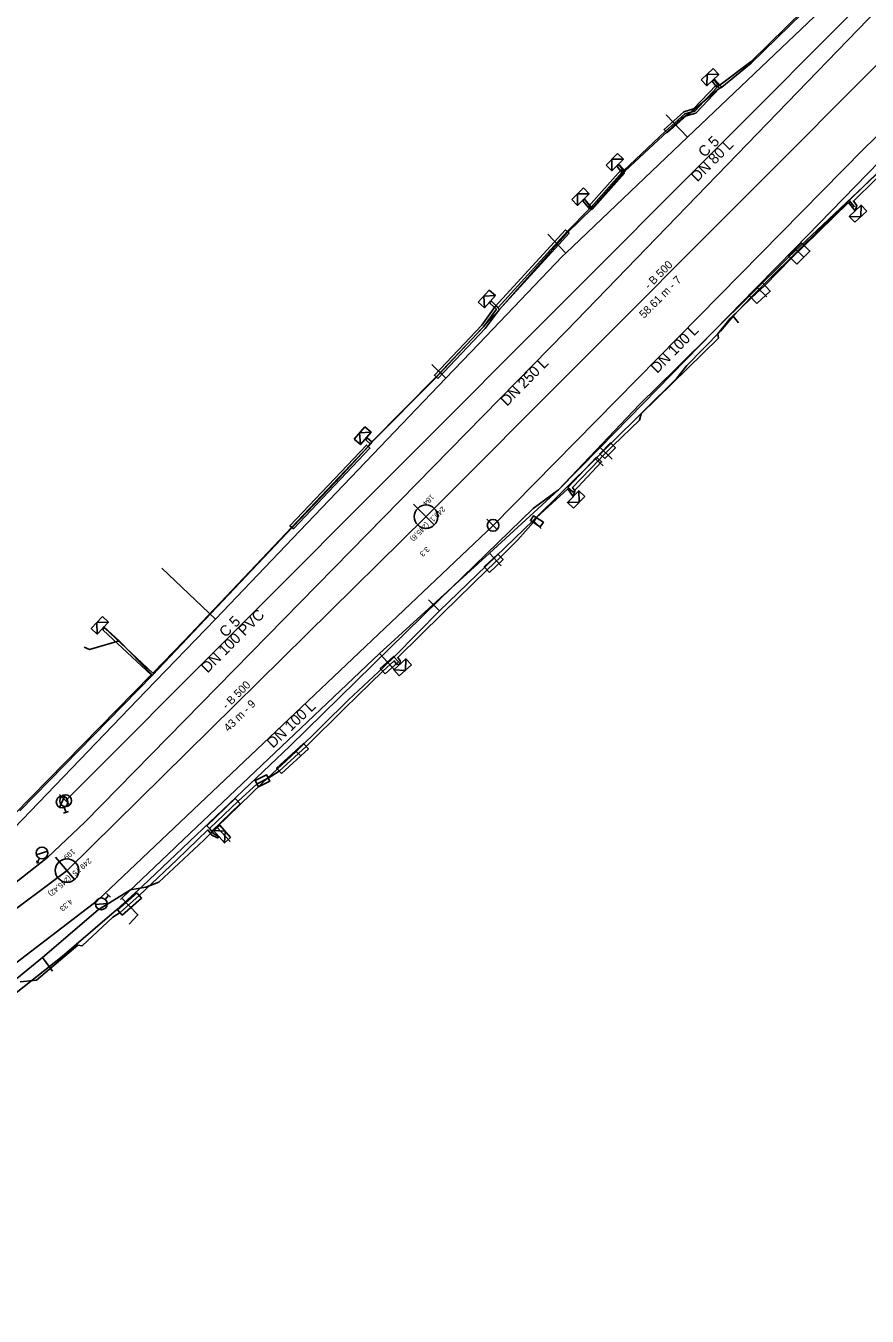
# Model space of a CAD drawing. Extents: x -600636 to -600148, y -1203980 to -1203569.
# Drawn here: x -600456.1 to -600384.3, y -1203740.1 to -1203630.1 of the extents above; entities that cross this region are included whole.
import ezdxf

# ---------------------------------------------------------------- set-up
doc = ezdxf.new("R2010")
doc.units = 0
for name, color, linetype in [('Cetin zam průběh', 7, 'Continuous'), ('EON podzemní NN', 7, 'Continuous'), ('GasNet NTL', 7, 'Continuous'), ('Implicitní', 7, 'Continuous'), ('VaK Břeclav_kanalizace', 7, 'Continuous'), ('VaK Břeclav_kanalizace_popis', 7, 'Continuous'), ('Vak Břeclav_vodovod', 7, 'Continuous'), ('Vak Břeclav_vodovod_popis', 7, 'Continuous'), ('Vrstva 9', 7, 'Continuous')]:
    doc.layers.add(name, color=color, linetype=linetype)

# ---------------------------------------------------------------- blocks, each defined once
blk = doc.blocks.new('NN630')
at = {"layer": 'Vrstva 9'}
for points in [[(0, -0.7), (-0.7, 0)], [(-0.7, -0.7), (-0.7, 0), (0.7, 0), (0.7, -0.7)], [(-0.7, -0.7), (0.7, -0.7)], [(0, -0.7), (0.7, 0)]]:
    blk.add_lwpolyline(points, dxfattribs=at)
blk = doc.blocks.new('MoSymbol 2')
at = {"layer": 'Implicitní'}
blk.add_line((0, 0.0005), (0, -0.00075), dxfattribs=at)
blk.add_circle((0, 0), 0.0005, dxfattribs=at)
blk = doc.blocks.new('MoSymbol 3')
at = {"layer": 'Implicitní'}
for p, q in [((-0.000365, -0.000365), (0.000365, 0.000365)), ((-0.000225, 0.00095), (0.000225, 0.00095)), ((0, 0.00095), (0, 0.0005))]:
    blk.add_line(p, q, dxfattribs=at)
blk.add_circle((0, 0), 0.0005, dxfattribs=at)
blk = doc.blocks.new('MoSymbol 5')
at = {"layer": 'Implicitní'}
for p, q in [((-0.000365, -0.000365), (0.000365, 0.000365)), ((0, 0.00095), (0.0001, 0.0008))]:
    blk.add_line(p, q, dxfattribs=at)
blk.add_lwpolyline([(0, 0.0005), (0, 0.00095), (-0.0001, 0.0008)], dxfattribs=at)
blk.add_circle((0, 0), 0.0005, dxfattribs=at)

msp = doc.modelspace()

# ---------------------------------------------------------------- linework, layer by layer
at = {"layer": 'Cetin zam průběh'}
for points in [[(-600403.75, -1203662.4), (-600400.59, -1203659.29), (-600391.04, -1203649.83), (-600378.25, -1203637.79), (-600376.97, -1203637.47), (-600375.66, -1203637.95), (-600375.36, -1203637.74), (-600369.01, -1203633.38), (-600361.52, -1203627.61), (-600348.82, -1203618.06), (-600335.53, -1203608.82), (-600318.11, -1203596.27), (-600313.64, -1203592.14)], [(-600396.73, -1203635.32), (-600394.24, -1203633.29), (-600389.88, -1203629.05)], [(-600385.87, -1203644.99), (-600379.24, -1203638.53), (-600378.07, -1203637.95), (-600377.04, -1203637.82), (-600374.96, -1203638.83), (-600373.66, -1203638.86), (-600369.62, -1203634.3), (-600368.09, -1203632.74)], [(-600396.73, -1203635.32), (-600397.41, -1203634.6)], [(-600404.98, -1203642.46), (-600400.14, -1203637.98), (-600399.49, -1203637.58), (-600397.06, -1203635.49), (-600396.73, -1203635.32)], [(-600399.49, -1203637.58), (-600397.06, -1203635.49)], [(-600404.98, -1203642.46), (-600405.35, -1203642.11), (-600405.51, -1203641.95)], [(-600407.82, -1203645.71), (-600404.98, -1203642.46)], [(-600407.82, -1203645.71), (-600408.44, -1203644.89)], [(-600395.78, -1203654.85), (-600394.24, -1203653.23), (-600393.19, -1203652.19), (-600392.21, -1203651.23), (-600390.95, -1203650.01), (-600389.97, -1203649.02), (-600385.87, -1203644.99)], [(-600385.87, -1203644.99), (-600385.42, -1203645.53)], [(-600415.71, -1203654.29), (-600409.87, -1203647.71), (-600407.82, -1203645.71)], [(-600421.21, -1203660.21), (-600415.71, -1203654.29), (-600409.87, -1203647.71)], [(-600390.95, -1203650.01), (-600389.97, -1203649.02)], [(-600394.24, -1203653.23), (-600393.19, -1203652.19)], [(-600426.6, -1203665.62), (-600421.21, -1203660.21), (-600415.71, -1203654.29)], [(-600415.71, -1203654.29), (-600416.41, -1203653.56)], [(-600407.51, -1203667.04), (-600407.25, -1203666.78), (-600406.25, -1203665.78), (-600400.57, -1203660.14), (-600399.71, -1203659.07), (-600396.85, -1203656.15), (-600395.78, -1203654.85)], [(-600395.78, -1203654.85), (-600395.31, -1203655.42)], [(-600412.83, -1203671.25), (-600410.66, -1203669.68), (-600403.75, -1203662.4)], [(-600426.6, -1203665.62), (-600426.99, -1203665.22)], [(-600445.32, -1203685.49), (-600433.34, -1203672.82), (-600429.69, -1203669.02), (-600426.84, -1203665.93), (-600426.6, -1203665.62)], [(-600433.34, -1203672.82), (-600429.69, -1203669.02), (-600426.84, -1203665.93)], [(-600407.25, -1203666.78), (-600406.25, -1203665.78)], [(-600412.82, -1203672.3), (-600407.51, -1203667.04)], [(-600407.51, -1203667.04), (-600406.87, -1203667.62)], [(-600433.58, -1203691.53), (-600420.86, -1203679.06), (-600412.83, -1203671.25)], [(-600420.82, -1203679.99), (-600412.82, -1203672.3)], [(-600412.82, -1203672.3), (-600412.16, -1203672.98)], [(-600421.75, -1203679.05), (-600420.82, -1203679.99)], [(-600433.06, -1203691.99), (-600428.59, -1203687.58), (-600425.61, -1203684.8), (-600424.64, -1203683.87), (-600420.82, -1203679.99)], [(-600448.15, -1203682.56), (-600449.48, -1203681.33)], [(-600448.15, -1203682.56), (-600450.67, -1203683.28), (-600451.15, -1203683.08)], [(-600445.32, -1203685.49), (-600448.15, -1203682.56)], [(-600424.64, -1203683.87), (-600425.61, -1203684.8)], [(-600456.63, -1203697.04), (-600445.32, -1203685.49)], [(-600446.15, -1203703.46), (-600433.58, -1203691.53)], [(-600439.83, -1203698.44), (-600435.92, -1203694.67), (-600433.06, -1203691.99)], [(-600433.06, -1203691.99), (-600435.92, -1203694.67)], [(-600433.06, -1203691.99), (-600432.67, -1203692.34)], [(-600454.7, -1203709.55), (-600449.93, -1203705.5), (-600447.19, -1203703.78), (-600445.87, -1203703.57), (-600444.77, -1203703.13), (-600440.93, -1203699.54), (-600439.83, -1203698.44)], [(-600440.93, -1203699.54), (-600439.83, -1203698.44)], [(-600439.83, -1203698.44), (-600438.69, -1203699.66)], [(-600453.01, -1203709.48), (-600448.37, -1203705.5), (-600446.15, -1203703.46)], [(-600447.19, -1203703.78), (-600445.87, -1203703.57)], [(-600490.14, -1203736.91), (-600480.27, -1203730.01), (-600469.5, -1203722.46), (-600453.01, -1203709.48)], [(-600465.84, -1203718.51), (-600459.73, -1203713.66), (-600454.7, -1203709.55)], [(-600454.7, -1203709.55), (-600453.84, -1203710.72)]]:
    msp.add_lwpolyline(points, dxfattribs=at)
at = {"layer": 'EON podzemní NN'}
for points in [[(-600457.12, -1203697.36), (-600445.42, -1203685.44), (-600449.51, -1203681.63), (-600449.55, -1203681.46), (-600449.38, -1203681.48), (-600445.28, -1203685.3), (-600442.61, -1203682.55), (-600433.43, -1203672.87), (-600426.9, -1203665.99), (-600426.73, -1203665.74), (-600427.09, -1203665.43), (-600427.11, -1203665.28), (-600426.96, -1203665.28), (-600426.6, -1203665.59), (-600421.1, -1203660.04), (-600417.07, -1203655.76), (-600415.96, -1203654.26), (-600416.51, -1203653.77), (-600416.52, -1203653.62), (-600416.37, -1203653.62), (-600415.83, -1203654.11), (-600409.92, -1203647.64), (-600408.02, -1203645.71), (-600408.58, -1203645.04), (-600408.55, -1203644.92), (-600408.42, -1203644.91), (-600407.88, -1203645.56), (-600405.26, -1203642.62), (-600405.66, -1203642.09), (-600405.62, -1203641.97), (-600405.5, -1203641.97), (-600405.12, -1203642.47), (-600401.53, -1203639.09), (-600399.88, -1203637.61), (-600399.05, -1203637.37), (-600397.15, -1203635.36), (-600397.52, -1203634.86), (-600397.5, -1203634.73), (-600397.36, -1203634.75), (-600397, -1203635.23), (-600394.24, -1203633.14), (-600388.26, -1203627.25)], [(-600378.11, -1203637.77), (-600385.51, -1203645.05), (-600385.21, -1203645.42), (-600385.36, -1203645.87), (-600385.93, -1203645.18), (-600389.78, -1203648.91), (-600390.81, -1203649.94), (-600393.06, -1203652.24), (-600394.21, -1203653.31), (-600396.01, -1203655.07), (-600397.08, -1203656.37), (-600397.03, -1203656.73), (-600403.62, -1203663.18), (-600403.76, -1203663.72), (-600406.01, -1203665.89), (-600406.92, -1203666.81), (-600407.2, -1203667.1), (-600409.47, -1203669.48), (-600409.27, -1203669.77), (-600409.42, -1203670.25), (-600409.88, -1203669.6), (-600412.56, -1203672.03), (-600412.83, -1203672.46), (-600414.13, -1203673.94), (-600415.59, -1203675.39), (-600416.75, -1203676.49), (-600420.53, -1203680.19), (-600424.39, -1203683.98), (-600424.17, -1203684.26), (-600424.2, -1203684.55), (-600424.45, -1203684.56), (-600424.68, -1203684.26), (-600425.66, -1203685.15), (-600428.94, -1203688.31), (-600432.21, -1203691.55), (-600434.51, -1203693.65), (-600435.44, -1203694.26), (-600436.39, -1203694.74), (-600438, -1203696.22), (-600440.45, -1203698.54), (-600440.11, -1203698.98), (-600439.93, -1203699.08), (-600439.63, -1203699.25), (-600439.77, -1203699.36), (-600440.24, -1203699.13), (-600440.59, -1203698.68), (-600443.24, -1203701.22), (-600446.43, -1203704.26), (-600448.06, -1203705.72), (-600448.7, -1203706.12), (-600451.32, -1203708.56), (-600451.68, -1203708.5), (-600455.19, -1203711.49), (-600456.59, -1203711.62)]]:
    msp.add_lwpolyline(points, dxfattribs=at)
for points in [[(-600401.4, -1203639.24), (-600401.66, -1203638.94), (-600399.98, -1203637.43), (-600399.16, -1203637.19), (-600397.22, -1203635.15), (-600396.94, -1203635.43), (-600398.94, -1203637.55), (-600399.78, -1203637.79)], [(-600407.8, -1203645.77), (-600408.1, -1203645.51), (-600405.34, -1203642.41), (-600405.04, -1203642.67)], [(-600420.95, -1203660.18), (-600421.25, -1203659.9), (-600417.22, -1203655.63), (-600416.06, -1203654.05), (-600410.07, -1203647.51), (-600409.77, -1203647.78), (-600415.74, -1203654.31), (-600416.93, -1203655.91)], [(-600390.33, -1203650.43), (-600391.04, -1203649.72), (-600389.93, -1203648.61), (-600389.22, -1203649.31)], [(-600393.76, -1203653.79), (-600394.44, -1203653.06), (-600393.29, -1203652), (-600392.61, -1203652.73)], [(-600433.29, -1203673.01), (-600433.58, -1203672.73), (-600427.05, -1203665.85), (-600426.76, -1203666.13)], [(-600406.73, -1203667.01), (-600407.15, -1203666.59), (-600406.24, -1203665.67), (-600405.82, -1203666.08)], [(-600409.43, -1203669.87), (-600409.86, -1203669.47), (-600407.42, -1203666.89), (-600406.99, -1203667.29)], [(-600412.22, -1203672.84), (-600413.07, -1203672.3), (-600412.81, -1203671.9), (-600411.96, -1203672.43)], [(-600416.56, -1203676.71), (-600417, -1203676.25), (-600415.84, -1203675.15), (-600415.4, -1203675.62)], [(-600425.46, -1203685.36), (-600425.88, -1203684.91), (-600424.75, -1203683.88), (-600424.33, -1203684.34)], [(-600434.3, -1203693.86), (-600434.72, -1203693.4), (-600432.42, -1203691.3), (-600432, -1203691.76)], [(-600436.26, -1203695.01), (-600436.54, -1203694.45), (-600435.59, -1203693.97), (-600435.31, -1203694.52)], [(-600440.25, -1203698.78), (-600440.68, -1203698.34), (-600438.24, -1203696), (-600437.82, -1203696.45)], [(-600446.64, -1203704.03), (-600446.24, -1203704.49), (-600447.89, -1203705.93), (-600448.28, -1203705.48)]]:
    msp.add_lwpolyline(points, close=True, dxfattribs=at)
at = {"layer": 'GasNet NTL'}
for points in [[(-600376.52, -1203617.62), (-600381.81, -1203622.65), (-600388.25, -1203628.77), (-600399.65, -1203639.6), (-600410.04, -1203649.48), (-600410.35, -1203649.77), (-600417.47, -1203657.21), (-600420.27, -1203660.14), (-600432.74, -1203673.17), (-600439.94, -1203680.7), (-600445.87, -1203686.85), (-600458.57, -1203700.01), (-600466.75, -1203707.26), (-600469.55, -1203709.74), (-600472.59, -1203712.26), (-600475.67, -1203714.29), (-600481.14, -1203718.36), (-600486.68, -1203722.48)], [(-600363.91, -1203626.79), (-600366.43, -1203628.72), (-600368.49, -1203630.18), (-600377.69, -1203636.35), (-600377.83, -1203636.45), (-600379.12, -1203637.4), (-600390.52, -1203649.08), (-600393.75, -1203652.39), (-600407.12, -1203666.06), (-600410.69, -1203669.71), (-600416.55, -1203675.06), (-600425.93, -1203683.63), (-600443.22, -1203700.03), (-600443.4, -1203700.21), (-600447.92, -1203704.5), (-600448.05, -1203704.62)], [(-600401.47, -1203637.68), (-600399.65, -1203639.6)], [(-600411.58, -1203647.86), (-600410.04, -1203649.48)], [(-600390.52, -1203649.08), (-600389.75, -1203649.84)], [(-600393.75, -1203652.39), (-600392.91, -1203653.22)], [(-600421.47, -1203658.98), (-600420.27, -1203660.14)], [(-600407.12, -1203666.06), (-600406.09, -1203667.07)], [(-600416.55, -1203675.06), (-600415.56, -1203676.14)], [(-600444.5, -1203676.34), (-600439.94, -1203680.7)], [(-600425.93, -1203683.63), (-600424.61, -1203685.07)], [(-600447.92, -1203704.5), (-600446.55, -1203705.92), (-600447.31, -1203706.72)]]:
    msp.add_lwpolyline(points, dxfattribs=at)
at = {"layer": 'VaK Břeclav_kanalizace'}
for p, q in [((-600421.97, -1203671.96), (-600380.57, -1203630.48)), ((-600452.6, -1203702.14), (-600421.97, -1203671.96)), ((-600486.46, -1203727.53), (-600452.6, -1203702.14))]:
    msp.add_line(p, q, dxfattribs=at)
at = {"layer": 'Vak Břeclav_vodovod'}
for p, q in [((-600370.99, -1203614.29), (-600423.62, -1203667.02)), ((-600384.65, -1203640.63), (-600377.98, -1203634.08)), ((-600416.25, -1203672.7), (-600384.65, -1203640.63)), ((-600423.62, -1203667.02), (-600452.72, -1203696.18)), ((-600450.01, -1203704.7), (-600416.25, -1203672.7))]:
    msp.add_line(p, q, dxfattribs=at)
for points in [[(-600372.22, -1203617.99), (-600384.28, -1203629.56), (-600410.01, -1203656.15), (-600451.09, -1203698.02), (-600454.25, -1203701.01)], [(-600454.25, -1203701.01), (-600472.2, -1203715.15), (-600488.66, -1203727.34), (-600496.91, -1203733.12), (-600525.43, -1203753.34), (-600551.89, -1203771.85), (-600568.7, -1203781.3)], [(-600529.07, -1203761.9), (-600506.65, -1203745.16), (-600494.67, -1203737.19), (-600466.59, -1203717.37), (-600450.01, -1203704.7)]]:
    msp.add_lwpolyline(points, dxfattribs=at)

# ---------------------------------------------------------------- block references
at = {"layer": 'EON podzemní NN'}
for p, rotation in [((-600397.5, -1203634.73), -135.7367250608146), ((-600405.62, -1203641.97), -134.66854715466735), ((-600408.55, -1203644.92), -134.98879443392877), ((-600385.36, -1203645.87), 43.5564138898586), ((-600416.52, -1203653.62), -132.08916115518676), ((-600427.11, -1203665.28), -130.81508335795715), ((-600409.42, -1203670.25), 46.18675277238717), ((-600449.55, -1203681.46), -132.95207212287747), ((-600424.2, -1203684.55), 42.05731670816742), ((-600439.63, -1203699.25), 130.97087773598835)]:
    msp.add_blockref('NN630', p, dxfattribs=dict(at, rotation=rotation))
at = {"layer": 'VaK Břeclav_kanalizace'}
for p, xscale, yscale, rotation in [((-600421.97, -1203671.96), 1999.750031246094, 1999.7500312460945, -135.1841039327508), ((-600452.6, -1203702.14), 1999.7500312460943, 1999.7500312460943, -139.28088320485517)]:
    msp.add_blockref('MoSymbol 2', p, dxfattribs=dict(at, xscale=xscale, yscale=yscale, rotation=rotation))
at = {"layer": 'Vak Břeclav_vodovod'}
for name, p, xscale, yscale, rotation in [('MoSymbol 2', (-600416.25, -1203672.7), 999.8750156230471, 999.8750156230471, -135.55570801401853), ('MoSymbol 3', (-600453.02, -1203696.29), 999.875015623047, 999.8750156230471, -159.07019206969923), ('MoSymbol 2', (-600452.72, -1203696.18), 999.8750156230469, 999.8750156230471, -134.9429196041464), ('MoSymbol 5', (-600454.73, -1203700.64), 999.8750156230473, 999.8750156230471, 153.43494881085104), ('MoSymbol 3', (-600449.67, -1203704.98), 999.8750156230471, 999.8750156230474, -40.2326517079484)]:
    msp.add_blockref(name, p, dxfattribs=dict(at, xscale=xscale, yscale=yscale, rotation=rotation))

# ---------------------------------------------------------------- texts
at = {"layer": 'VaK Břeclav_kanalizace_popis'}
for s, height, rotation, p in [('- B 500', 0.682, 45.0567, (-600402.95, -1203652.62)), ('58.61 m - 7', 0.6824, 45.0567, (-600403.38, -1203655.1)), ('184', 0.455, 224.8159, (-600421.53, -1203670.02)), ('249,1  (245,8)', 0.4549, 224.8159, (-600420.59, -1203671.05)), ('3.3', 0.455, 224.8159, (-600421.93, -1203674.48)), ('- B 500', 0.682, 44.5751, (-600438.98, -1203688.44)), ('43 m - 9', 0.682, 44.5751, (-600438.83, -1203690.34)), ('199', 0.455, 220.7191, (-600452.14, -1203700.25)), ('249,75  (245,42)', 0.4549, 220.7191, (-600450.75, -1203701.05)), ('4.33', 0.455, 220.7191, (-600452.35, -1203704.53))]:
    msp.add_text(s, height=height, rotation=rotation, dxfattribs=at).set_placement(p)
at = {"layer": 'Vak Břeclav_vodovod_popis'}
for s, rotation, p in [('DN 80 L', 45.0571, (-600398.82, -1203643.46)), ('C 5', 45.0571, (-600398.21, -1203641.38)), ('DN 100 L', 45.4202, (-600402.25, -1203659.79)), ('DN 250 L', 45.5415, (-600415.06, -1203662.59)), ('DN 100 PVC', 45.0571, (-600440.61, -1203685.34)), ('C 5', 45.0571, (-600439.07, -1203682.32)), ('DN 100 L', 43.4684, (-600435.03, -1203691.76))]:
    msp.add_text(s, height=0.91, rotation=rotation, dxfattribs=at).set_placement(p)

doc.saveas('drawing.dxf')
